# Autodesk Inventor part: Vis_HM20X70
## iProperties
Library Location: C:\Program Files\Autodesk\Inventor 6\content
Library: local
SubLibrary: ISO
Family: 5
Member: 910
Member Major Revision: 1
Member Minor Revision: 1
Comments: To add or edit properties for Autodesk Inventor files, use iProperties.
Created: 2008-02
Part Number: Vis_HM20X70
Vendor: Autodesk Inc.
Document SubType Name: Modeling
Designer: Pascal
Description: Boulon à tête hexagonale
Standard: ISO 4014 M20 x 80
Material: Stainless Steel, 440C
Alert: To add or edit properties for Autodesk Inventor files, use iProperties.
Control State: 0
Master: False
Checked Out: False
Shininess: 64.0
Length Units: 11269
Angle Units: 11279
Time Units: 11290
Mass Units: 11283
Length Display Precision: 3
Angle Display Precision: 2
Compacted: True
EGR: 1
Density: 0.0
Volumn: 0.0
Area: 0.0
PropertySet Name: Model Information
Author: Pascal
Revision Number: 1
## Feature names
1. Body [Revolution]
2. Head [Extrusion]
3. Chamfer1 [Revolution]
4. Chamfer2
